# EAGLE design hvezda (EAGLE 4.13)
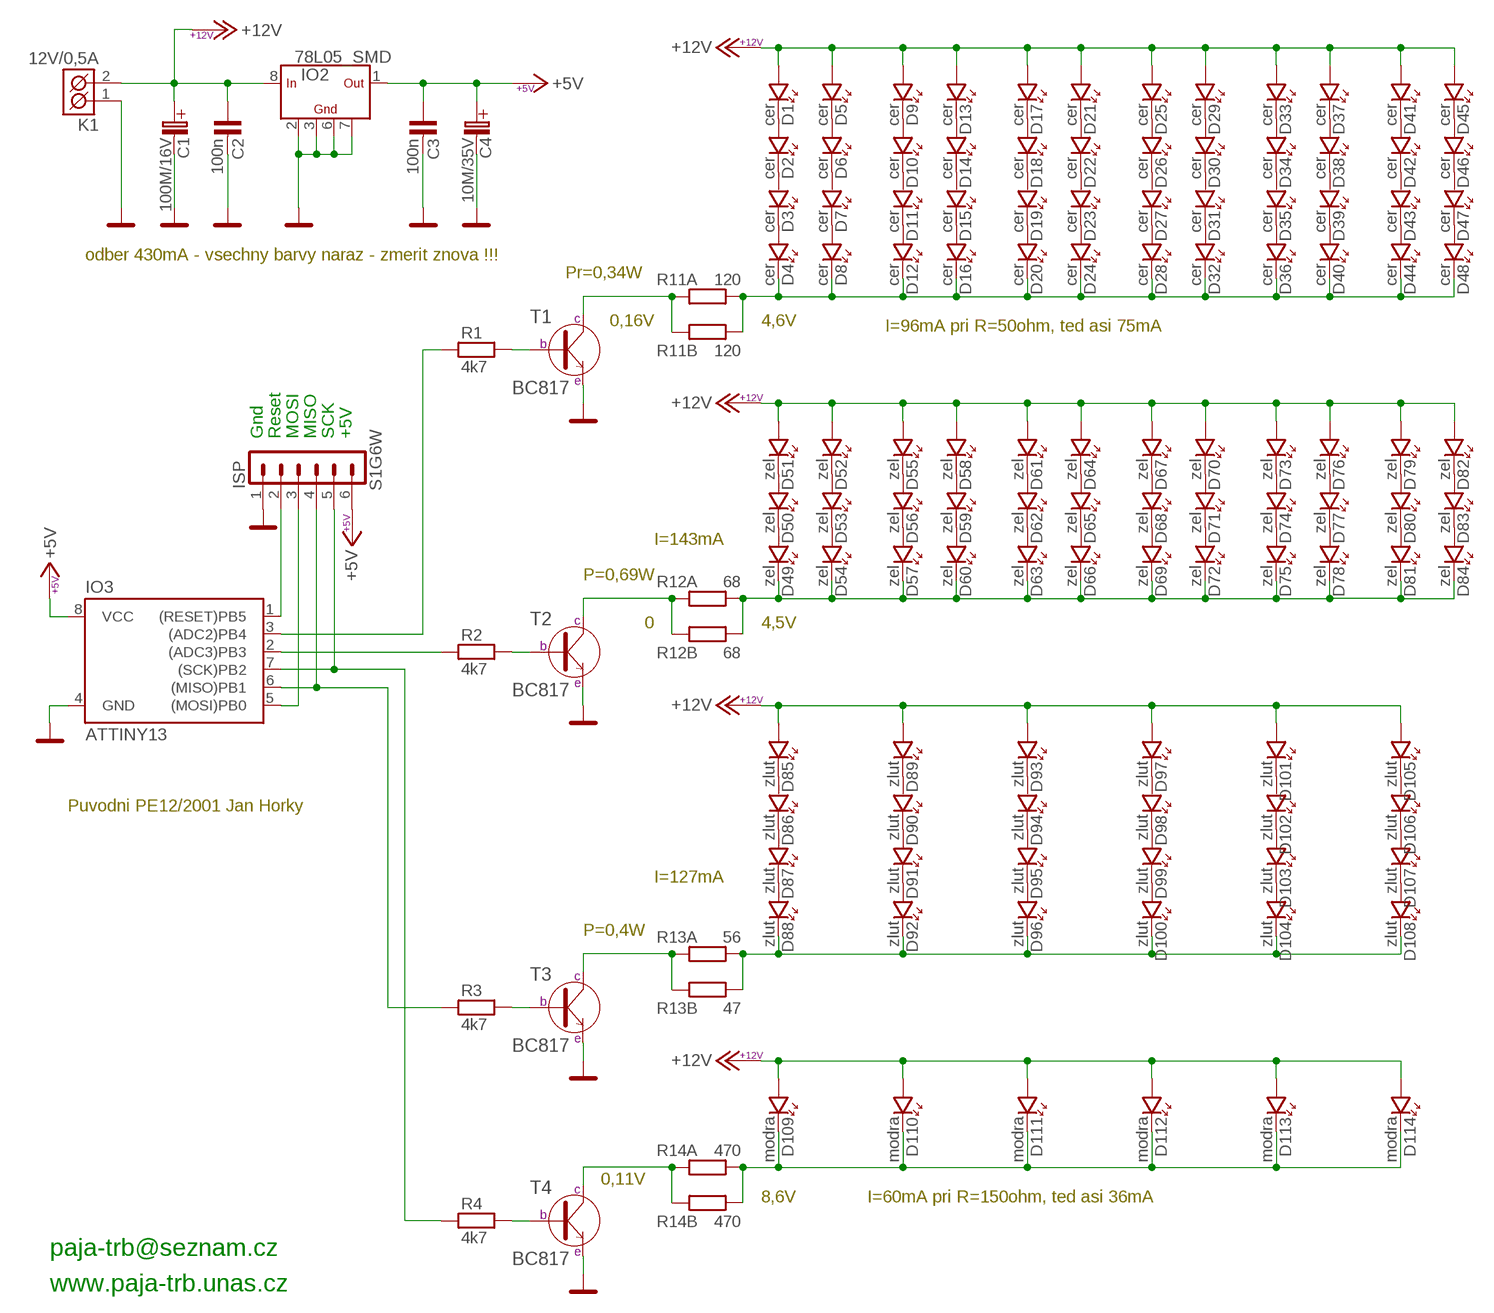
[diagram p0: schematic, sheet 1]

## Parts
C1  100M/16V  100M/16V_SMD  [C_EL-SMD_D]
C2  100n  C-KERAMIK_SMD_1206  [1206]
C3  100n  C-KERAMIK_SMD_1206  [1206]
C4  10M/35V  10M/35V_SMD  [C_EL-SMD_C]
D1  cer  LED_SMD_1206  [P1206]
D2  cer  LED_SMD_1206  [P1206]
D3  cer  LED_SMD_1206  [P1206]
D4  cer  LED_SMD_1206  [P1206]
D5  cer  LED_SMD_1206  [P1206]
D6  cer  LED_SMD_1206  [P1206]
D7  cer  LED_SMD_1206  [P1206]
D8  cer  LED_SMD_1206  [P1206]
D9  cer  LED_SMD_1206  [P1206]
D10  cer  LED_SMD_1206  [P1206]
D11  cer  LED_SMD_1206  [P1206]
D12  cer  LED_SMD_1206  [P1206]
D13  cer  LED_SMD_1206  [P1206]
D14  cer  LED_SMD_1206  [P1206]
D15  cer  LED_SMD_1206  [P1206]
D16  cer  LED_SMD_1206  [P1206]
D17  cer  LED_SMD_1206  [P1206]
D18  cer  LED_SMD_1206  [P1206]
D19  cer  LED_SMD_1206  [P1206]
D20  cer  LED_SMD_1206  [P1206]
D21  cer  LED_SMD_1206  [P1206]
D22  cer  LED_SMD_1206  [P1206]
D23  cer  LED_SMD_1206  [P1206]
D24  cer  LED_SMD_1206  [P1206]
D25  cer  LED_SMD_1206  [P1206]
D26  cer  LED_SMD_1206  [P1206]
D27  cer  LED_SMD_1206  [P1206]
D28  cer  LED_SMD_1206  [P1206]
D29  cer  LED_SMD_1206  [P1206]
D30  cer  LED_SMD_1206  [P1206]
D31  cer  LED_SMD_1206  [P1206]
D32  cer  LED_SMD_1206  [P1206]
D33  cer  LED_SMD_1206  [P1206]
D34  cer  LED_SMD_1206  [P1206]
D35  cer  LED_SMD_1206  [P1206]
D36  cer  LED_SMD_1206  [P1206]
D37  cer  LED_SMD_1206  [P1206]
D38  cer  LED_SMD_1206  [P1206]
D39  cer  LED_SMD_1206  [P1206]
D40  cer  LED_SMD_1206  [P1206]
D41  cer  LED_SMD_1206  [P1206]
D42  cer  LED_SMD_1206  [P1206]
D43  cer  LED_SMD_1206  [P1206]
D44  cer  LED_SMD_1206  [P1206]
D45  cer  LED_SMD_1206  [P1206]
D46  cer  LED_SMD_1206  [P1206]
D47  cer  LED_SMD_1206  [P1206]
D48  cer  LED_SMD_1206  [P1206]
D49  zel  LED_SMD_1206  [P1206]
D50  zel  LED_SMD_1206  [P1206]
D51  zel  LED_SMD_1206  [P1206]
D52  zel  LED_SMD_1206  [P1206]
D53  zel  LED_SMD_1206  [P1206]
D54  zel  LED_SMD_1206  [P1206]
D55  zel  LED_SMD_1206  [P1206]
D56  zel  LED_SMD_1206  [P1206]
D57  zel  LED_SMD_1206  [P1206]
D58  zel  LED_SMD_1206  [P1206]
D59  zel  LED_SMD_1206  [P1206]
D60  zel  LED_SMD_1206  [P1206]
D61  zel  LED_SMD_1206  [P1206]
D62  zel  LED_SMD_1206  [P1206]
D63  zel  LED_SMD_1206  [P1206]
D64  zel  LED_SMD_1206  [P1206]
D65  zel  LED_SMD_1206  [P1206]
D66  zel  LED_SMD_1206  [P1206]
D67  zel  LED_SMD_1206  [P1206]
D68  zel  LED_SMD_1206  [P1206]
D69  zel  LED_SMD_1206  [P1206]
D70  zel  LED_SMD_1206  [P1206]
D71  zel  LED_SMD_1206  [P1206]
D72  zel  LED_SMD_1206  [P1206]
D73  zel  LED_SMD_1206  [P1206]
D74  zel  LED_SMD_1206  [P1206]
D75  zel  LED_SMD_1206  [P1206]
D76  zel  LED_SMD_1206  [P1206]
D77  zel  LED_SMD_1206  [P1206]
D78  zel  LED_SMD_1206  [P1206]
D79  zel  LED_SMD_1206  [P1206]
D80  zel  LED_SMD_1206  [P1206]
D81  zel  LED_SMD_1206  [P1206]
D82  zel  LED_SMD_1206  [P1206]
D83  zel  LED_SMD_1206  [P1206]
D84  zel  LED_SMD_1206  [P1206]
D85  zlut  LED_SMD_1206  [P1206]
D86  zlut  LED_SMD_1206  [P1206]
D87  zlut  LED_SMD_1206  [P1206]
D88  zlut  LED_SMD_1206  [P1206]
D89  zlut  LED_SMD_1206  [P1206]
D90  zlut  LED_SMD_1206  [P1206]
D91  zlut  LED_SMD_1206  [P1206]
D92  zlut  LED_SMD_1206  [P1206]
D93  zlut  LED_SMD_1206  [P1206]
D94  zlut  LED_SMD_1206  [P1206]
D95  zlut  LED_SMD_1206  [P1206]
D96  zlut  LED_SMD_1206  [P1206]
D97  zlut  LED_SMD_1206  [P1206]
D98  zlut  LED_SMD_1206  [P1206]
D99  zlut  LED_SMD_1206  [P1206]
D100  zlut  LED_SMD_1206  [P1206]
D101  zlut  LED_SMD_1206  [P1206]
D102  zlut  LED_SMD_1206  [P1206]
D103  zlut  LED_SMD_1206  [P1206]
D104  zlut  LED_SMD_1206  [P1206]
D105  zlut  LED_SMD_1206  [P1206]
D106  zlut  LED_SMD_1206  [P1206]
D107  zlut  LED_SMD_1206  [P1206]
D108  zlut  LED_SMD_1206  [P1206]
D109  modra  LED_SMD_1206  [P1206]
D110  modra  LED_SMD_1206  [P1206]
D111  modra  LED_SMD_1206  [P1206]
D112  modra  LED_SMD_1206  [P1206]
D113  modra  LED_SMD_1206  [P1206]
D114  modra  LED_SMD_1206  [P1206]
IO2  78L05_SMD  78L_SMD-SO8  [SO08]
IO3  ATTINY13  [SOIC08]
ISP  S1G6W  S1G6_JUMP  [S1G6_JUM]
K1  12V/0,5A  ARK500/2  [ARK500/2]
R1  4k7  R_SMD_1206  [1206]
R2  4k7  R_SMD_1206  [1206]
R3  4k7  R_SMD_1206  [1206]
R4  4k7  R_SMD_1206  [1206]
R11A  120  R_SMD_1206  [1206]
R11B  120  R_SMD_1206  [1206]
R12A  68  R_SMD_1206  [1206]
R12B  68  R_SMD_1206  [1206]
R13A  56  R_SMD_1206  [1206]
R13B  47  R_SMD_1206  [1206]
R14A  470  R_SMD_1206  [1206]
R14B  470  R_SMD_1206  [1206]
T1  BC817  [SOT-23]
T2  BC817  [SOT-23]
T3  BC817  [SOT-23]
T4  BC817  [SOT-23]

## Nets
+5V: C3.1 C4.+(C_EL+) IO2.1(OUT) IO3.8(VCC) ISP.6
+12V: C1.+(C_EL+) C2.1 D1.A D5.A D9.A D13.A D17.A D21.A D25.A D29.A D33.A D37.A D41.A D45.A D51.A D52.A D55.A D58.A D61.A D64.A D67.A D70.A D73.A D76.A D79.A D82.A D85.A D89.A D93.A D97.A D101.A D105.A D109.A D110.A D111.A D112.A D113.A D114.A IO2.8(IN) K1.2(K2)
GND: C1.-(C_EL-) C2.2 C3.2 C4.-(C_EL-) IO2.2(GND) IO2.3(GND) IO2.6(GND) IO2.7(GND) IO3.4(GND) ISP.1 K1.1(K1) T1.1(E) T2.1(E) T3.1(E) T4.1(E)
K_CER: D4.K D8.K D12.K D16.K D20.K D24.K D28.K D32.K D36.K D40.K D44.K D48.K R11A.2 R11B.2
K_NEVIM: D109.K D110.K D111.K D112.K D113.K D114.K R14A.2 R14B.2
K_ZEL: D49.K D54.K D57.K D60.K D63.K D66.K D69.K D72.K D75.K D78.K D81.K D84.K R12A.2 R12B.2
K_ZLUT: D88.K D92.K D96.K D100.K D104.K D108.K R13A.2 R13B.2
N$1: D1.K D2.A
N$2: D2.K D3.A
N$3: D3.K D4.A
N$4: D5.K D6.A
N$5: D50.A D51.K
N$6: D6.K D7.A
N$7: D9.K D10.A
N$8: D7.K D8.A
N$9: D10.K D11.A
N$10: D11.K D12.A
N$11: D13.K D14.A
N$12: D14.K D15.A
N$13: D15.K D16.A
N$14: D17.K D18.A
N$15: D18.K D19.A
N$16: D19.K D20.A
N$17: D21.K D22.A
N$18: D22.K D23.A
N$19: D23.K D24.A
N$20: D25.K D26.A
N$21: D26.K D27.A
N$22: D27.K D28.A
N$23: D29.K D30.A
N$24: D30.K D31.A
N$25: D31.K D32.A
N$26: D33.K D34.A
N$27: D34.K D35.A
N$28: D35.K D36.A
N$29: D37.K D38.A
N$30: D38.K D39.A
N$31: D39.K D40.A
N$32: D41.K D42.A
N$33: D42.K D43.A
N$34: D43.K D44.A
N$35: D45.K D46.A
N$36: D46.K D47.A
N$37: D47.K D48.A
N$38: D49.A D50.K
N$39: D52.K D53.A
N$40: D53.K D54.A
N$41: D55.K D56.A
N$42: D56.K D57.A
N$43: D58.K D59.A
N$44: D59.K D60.A
N$45: D61.K D62.A
N$46: D62.K D63.A
N$47: D64.K D65.A
N$48: D65.K D66.A
N$49: D67.K D68.A
N$50: D68.K D69.A
N$51: D70.K D71.A
N$52: D71.K D72.A
N$53: D73.K D74.A
N$54: D74.K D75.A
N$55: D76.K D77.A
N$56: D77.K D78.A
N$57: D79.K D80.A
N$58: D80.K D81.A
N$59: D82.K D83.A
N$60: D83.K D84.A
N$61: IO3.1((RESET)PB5) ISP.2
N$67: D85.K D86.A
N$68: D86.K D87.A
N$69: D87.K D88.A
N$71: D89.K D90.A
N$72: D90.K D91.A
N$73: D91.K D92.A
N$74: D93.K D94.A
N$75: D94.K D95.A
N$76: D95.K D96.A
N$77: D97.K D98.A
N$78: D98.K D99.A
N$79: D99.K D100.A
N$80: D101.K D102.A
N$81: D102.K D103.A
N$82: D103.K D104.A
N$83: D105.K D106.A
N$84: D106.K D107.A
N$85: D107.K D108.A
N$88: IO3.2((ADC3)PB3) R2.1
N$91: R3.2 T3.2(B)
N$92: R13A.1 R13B.1 T3.3(C)
N$93: R11A.1 R11B.1 T1.3(C)
N$94: R12A.1 R12B.1 T2.3(C)
N$95: R1.2 T1.2(B)
N$96: R2.2 T2.2(B)
N$97: IO3.3((ADC2)PB4) R1.1
N$98: IO3.5((MOSI)PB0) ISP.3
N$99: IO3.6((MISO)PB1) ISP.4 R3.1
N$121: R4.2 T4.2(B)
N$122: R14A.1 R14B.1 T4.3(C)
N$123: IO3.7((SCK)PB2) ISP.5 R4.1
Unconnected: IO2.4 IO2.5

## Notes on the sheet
- odber 430mA - vsechny barvy naraz - zmerit znova !!!
- Pr=0,34W
- 0,16V | 4,6V
- I=96mA pri R=50ohm, ted asi 75mA
- Gnd | Reset | MOSI | MISO | SCK | +5V
- I=143mA
- P=0,69W
- 0 | 4,5V
- Puvodni PE12/2001 Jan Horky
- I=127mA
- P=0,4W
- 0,11V
- 8,6V | I=60mA pri R=150ohm, ted asi 36mA
- paja-trb@seznam.cz
- www.paja-trb.unas.cz

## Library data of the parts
C1 = #PaJa_C-el_eagle413:100M/16V
C2 C3 = #PaJa_20:C-KERAMIK: Kondenzator - keramicky
C4 = #PaJa_C-el_eagle413:10M/35V
D1-D114 = #PaJa_20:LED: LED - jednobarevna
IO2 = #PaJa_22:78L??_SMD-SO8: Stabilizátor SMD - 100mA ?? - napeti => 05, 08, 09, 12, 15
IO3 = #PaJa_22:ATTINY13
ISP = __pokusy:S1G6_JUMP
K1 = __pokusy:ARK500/2: Svorkovnice - roztec 5mm - dvojita
R1-R4 R11A R11B R12A R12B R13A R13B R14A R14B = #PaJa_20:R: Rezistor
T1-T4 = #PaJa_20:BC817: SMD tranzistor - NPN - ekv. BC337

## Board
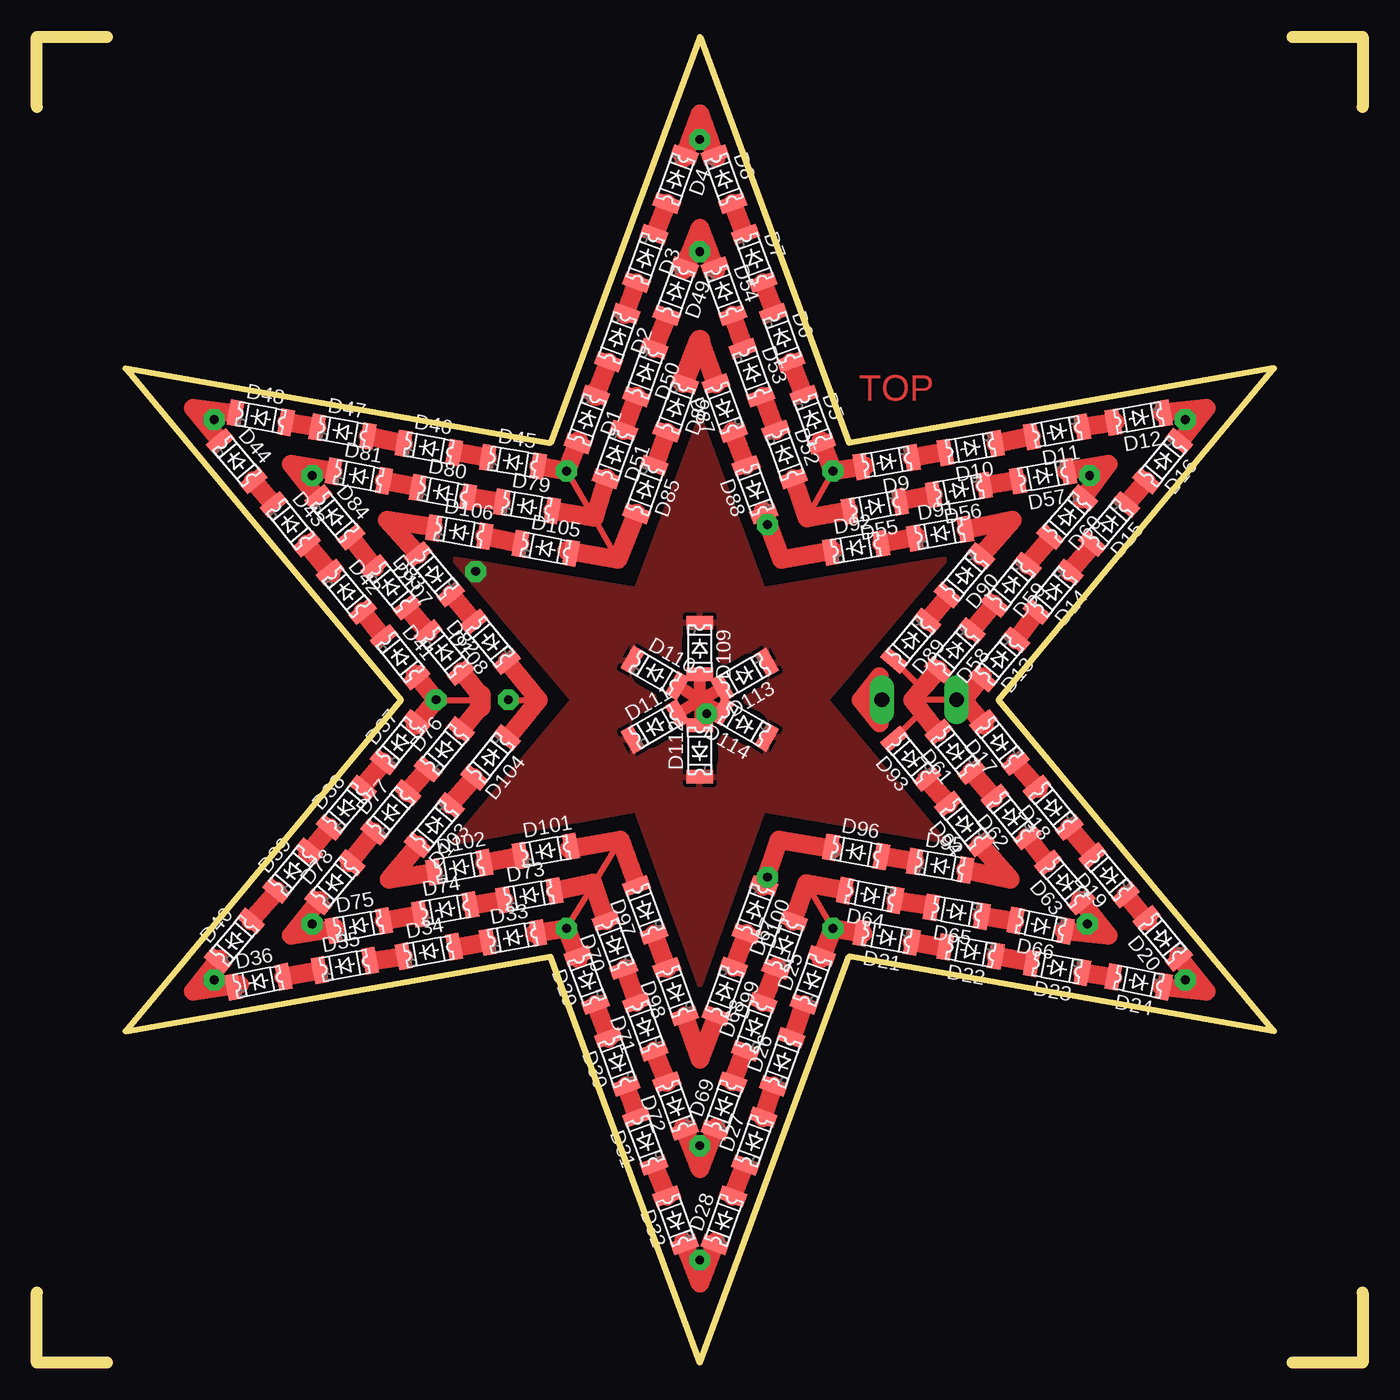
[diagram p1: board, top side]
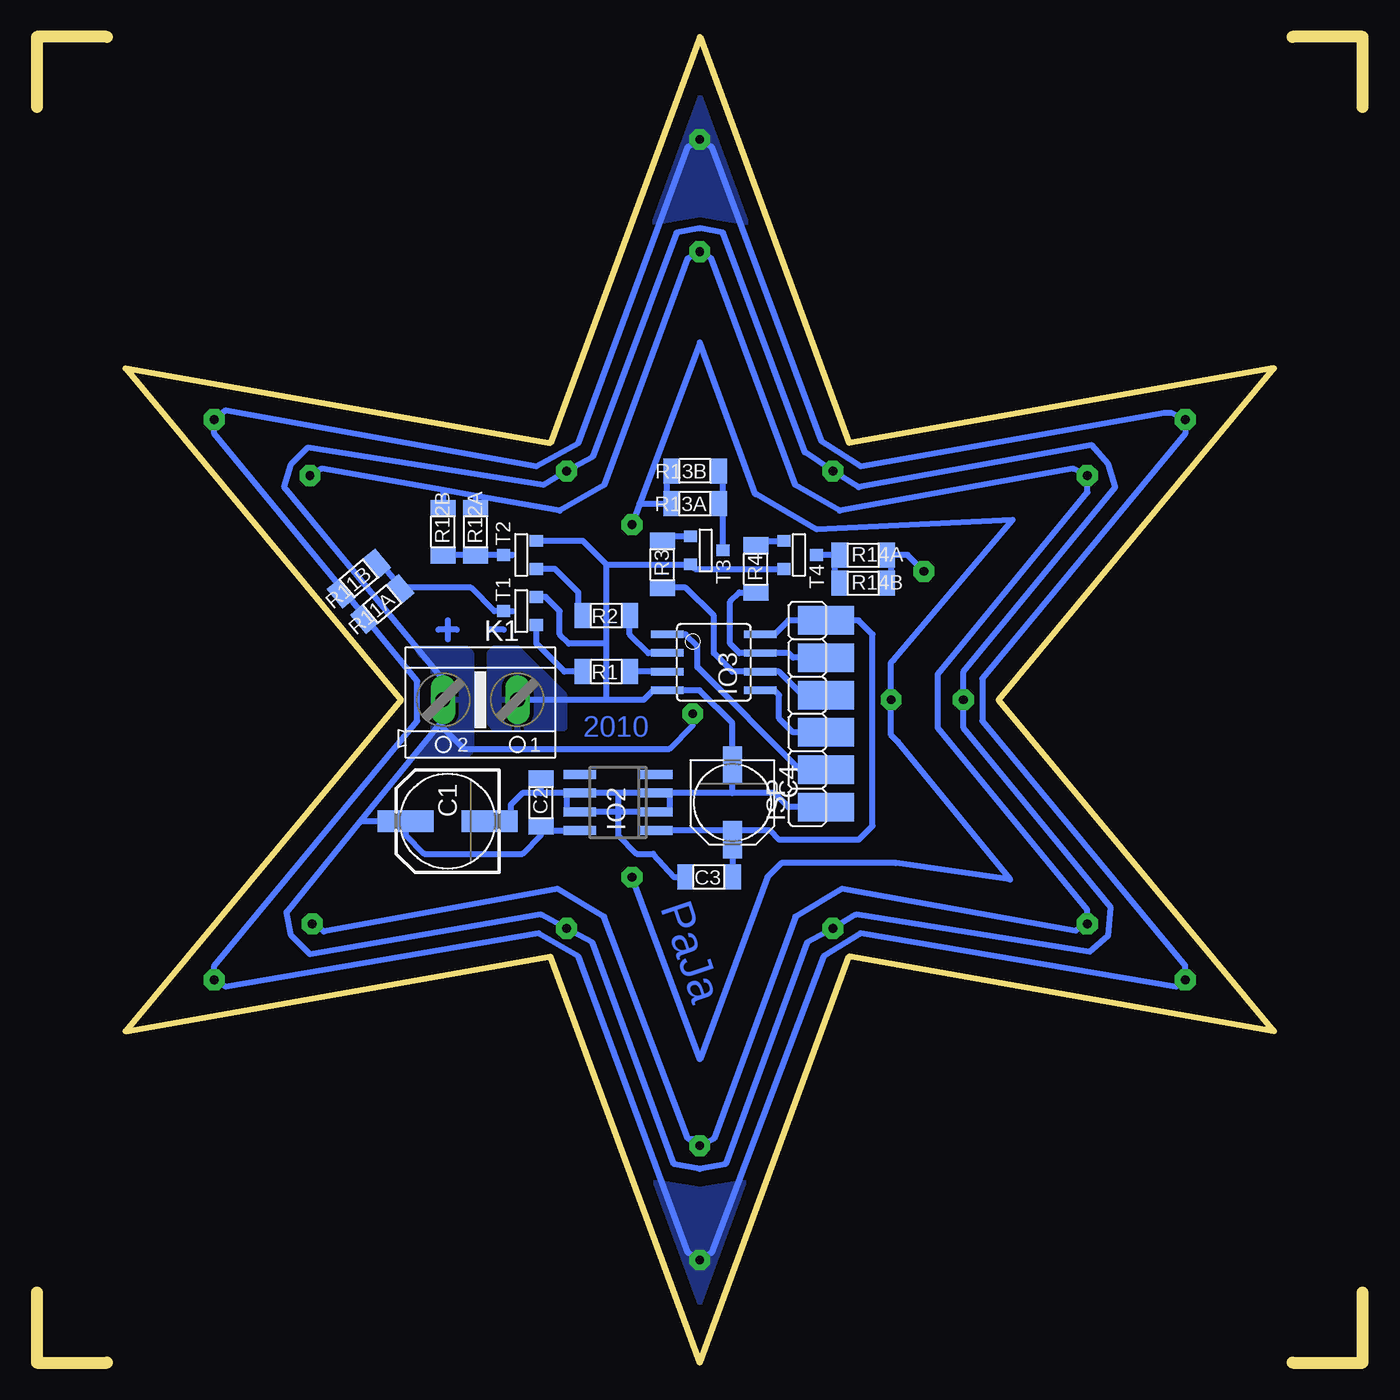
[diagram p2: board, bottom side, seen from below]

Size 90.17 x 90.17 mm. Coordinates in mm from the lower left corner, seen from the top.
Outline: 0,4.76 0,0 4.76,0
Outline: 85.41,0 90.17,0 90.17,4.76
Outline: 90.17,85.41 90.17,90.17 85.41,90.17
Outline: 4.76,90.17 0,90.17 0,85.41
Outline: 45.08,90.17 34.93,62.55 6.03,67.63 24.76,45.09 6.03,22.54 34.93,27.62 45.08,0 55.25,27.62 84.14,22.54 65.41,45.09 84.14,67.63 55.25,62.55 45.08,90.17
Copper layers (1*16): Top 0.035mm / dielectric 1.5mm / Bottom 0.035mm
Design rules "default": minimum track width 10mil, minimum drill 24mil, track to track 8mil, track to pad 8mil, pad to pad 8mil, via to via 8mil, smd to smd 8mil, copper to edge 40mil, drill to drill 8mil, minimum pad ring 10mil, minimum via ring 8mil, stop-mask expansion 4mil, vias tented up to drill 0mil, thermal gap 10mil
tRestrict: 3 lines

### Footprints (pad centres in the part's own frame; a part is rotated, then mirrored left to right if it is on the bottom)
C_EL-SMD_D = smd 3.81 x 1.473: + 2.857,0; - -2.857,0
1206 = smd 1.143 x 1.702: 1 -1.587,0; 2 1.587,0
C_EL-SMD_C = smd 2.54 x 1.27: + 2.54,0; - -2.54,0
P1206 = smd 0.914 x 1.778: A 1.905,0; K -1.587,0
SO08 = smd 0.6 x 2.2: 1 -1.905,-2.6; 2 -0.635,-2.6; 3 0.635,-2.6; 4 1.905,-2.6; 5 1.905,2.6; 6 0.635,2.6; 7 -0.635,2.6; 8 -1.905,2.6
SOIC08 = smd 2.2 x 0.5: 1 -3.154,1.905; 2 -3.154,0.645; 3 -3.154,-0.625; 4 -3.154,-1.895; 5 3.154,-1.905; 6 3.154,-0.635; 7 3.154,0.635; 8 3.154,1.905
S1G6_JUM = smd 1.93 x 3.81: 1 -6.35,-1.27; 2 -3.81,-1.27; 3 -1.27,-1.27; 4 1.27,-1.27; 5 3.81,-1.27; 6 6.35,-1.27
ARK500/2 = drill 1 pad 1.676 long: 1 -2.54,0; 2 2.54,0
SOT-23 = smd 0.787 x 0.889: 1 0.953,-0.953; 2 -0.953,-0.953; 3 0,1.27

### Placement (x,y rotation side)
C1  62.23,36.83 180 bottom
C2  55.88,38.1 90 bottom
C3  44.45,33.02 180 bottom
C4  42.86,38.1 270 bottom
D1  37.47,64.29 250 top
D2  39.53,69.85 250 top
D3  41.43,75.25 250 top
D4  43.5,80.65 250 top
D5  52.7,64.29 290 top
D6  50.64,69.85 290 top
D7  48.74,75.25 290 top
D8  46.67,80.65 290 top
D9  57.94,61.28 189.8 top
D10  63.66,62.23 190 top
D11  69.53,63.34 190.6 top
D12  75.09,64.29 190 top
D13  65.56,47.94 229.9 top
D14  69.21,52.55 230.1 top
D15  73.02,57.15 229.4 top
D16  76.68,61.44 230.4 top
D17  65.56,42.07 128.7 top
D18  69.21,37.62 129.3 top
D19  73.02,33.02 130.1 top
D20  76.68,28.73 129.4 top
D21  57.94,28.89 169.8 top
D22  63.66,27.94 169.9 top
D23  69.53,26.83 169.8 top
D24  75.09,25.88 169 top
D25  52.71,25.88 70 top
D26  50.64,20.32 70 top
D27  48.74,14.92 70 top
D28  46.67,9.53 70 top
D29  37.47,25.88 110 top
D30  39.53,20.32 110 top
D31  41.43,14.92 110 top
D32  43.5,9.53 110 top
D33  32.23,28.89 10.3 top
D34  26.51,27.94 10.8 top
D35  20.8,26.99 10.7 top
D36  14.92,25.88 11.4 top
D37  24.61,42.07 50.5 top
D38  20.96,37.62 49.8 top
D39  17.3,33.34 50.2 top
D40  13.33,28.57 50 top
D41  24.61,48.1 309.1 top
D42  20.96,52.55 309.4 top
D43  17.15,57.15 309.6 top
D44  13.49,61.44 310.2 top
D45  32.23,61.28 350.6 top
D46  26.51,62.23 349.8 top
D47  20.64,63.34 350 top
D48  15.08,64.29 349.5 top
D49  43.5,73.03 250 top
D50  41.43,67.47 250 top
D51  39.37,61.91 250 top
D52  50.8,61.91 290 top
D53  48.58,67.47 290 top
D54  46.67,73.02 290 top
D55  57.15,58.26 190.4 top
D56  62.87,59.37 190.3 top
D57  68.58,60.33 190.4 top
D58  62.55,48.58 229.6 top
D59  66.36,53.02 230.7 top
D60  70.17,57.63 229.1 top
D61  62.55,41.43 129.4 top
D62  66.36,36.99 129.3 top
D63  70.01,32.54 130.4 top
D64  56.83,31.75 169.2 top
D65  62.71,30.64 170.2 top
D66  68.42,29.69 168.4 top
D67  50.8,28.26 70 top
D68  48.74,22.7 70 top
D69  46.67,17.3 70 top
D70  39.37,28.26 110 top
D71  41.43,22.7 110 top
D72  43.5,17.3 110 top
D73  33.34,31.75 10.1 top
D74  27.62,30.8 10.3 top
D75  21.75,29.69 10.7 top
D76  27.62,41.59 50.3 top
D77  23.97,37.31 50.1 top
D78  20.16,32.54 50 top
D79  33.18,58.26 350.5 top
D80  27.46,59.21 349.5 top
D81  21.75,60.33 349.4 top
D82  27.62,48.42 309.6 top
D83  23.97,52.86 309.6 top
D84  20.16,57.63 309.9 top
D85  41.43,59.53 250 top
D86  43.5,65.09 250 top
D87  46.83,64.77 110 top
D88  48.9,59.21 110 top
D89  59.53,49.21 229.7 top
D90  63.18,53.66 229.8 top
D91  61.28,56.36 10 top
D92  55.56,55.4 9.5 top
D93  59.53,40.96 130 top
D94  63.18,36.51 129.2 top
D95  61.28,33.81 350.6 top
D96  55.56,34.77 349.6 top
D97  41.43,30.64 110 top
D98  43.5,25.08 110 top
D99  46.83,25.4 250 top
D100  48.9,30.96 250 top
D101  34.45,34.77 10.3 top
D102  28.58,33.66 10.5 top
D103  27.15,36.67 230.1 top
D104  30.96,41.28 230.8 top
D105  34.45,55.4 349.5 top
D106  28.57,56.52 350.7 top
D107  27.15,53.5 129.7 top
D108  30.96,48.89 129.5 top
D109  45.09,48.74 270 top
D110  41.91,46.99 330 top
D111  41.91,43.18 30 top
D112  45.08,41.43 90 top
D113  48.26,46.83 210 top
D114  48.26,43.34 150 top
IO2  50.64,38.1 90 bottom
IO3  44.13,47.62 0 bottom
ISP  37.78,44.13 90 bottom
K1  60.01,45.09 180 bottom
R1  51.44,46.99 180 bottom
R2  51.44,50.8 180 bottom
R3  47.62,54.29 90 bottom
R4  41.27,53.98 90 bottom
R11A  66.67,51.59 220 bottom
R11B  68.26,53.34 220 bottom
R12A  60.32,56.51 90 bottom
R12B  62.55,56.52 90 bottom
R13A  45.4,58.42 180 bottom
R13B  45.4,60.64 180 bottom
R14A  33.97,54.93 0 bottom
R14B  33.97,53.02 0 bottom
T1  57.15,51.12 90 bottom
T2  57.15,54.93 90 bottom
T3  44.77,55.24 270 bottom
T4  38.42,54.93 270 bottom

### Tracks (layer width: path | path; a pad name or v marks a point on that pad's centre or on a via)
+5V
  Bottom 0.406: 40.01,49.53 40.96,49.55 | 42.7,36.04 42.53,36.06 42.55,36.07 42.55,36.2 | 42.7,36.04 42.86,35.88 C4.+ 42.86,35.24 | 42.86,36.2 42.86,36.19 42.7,36.04 | 42.86,36.2 IO2.1 | 42.86,35.24 C3.1 | 42.86,35.24 | ISP.6 36.83,51.12 | ISP.6 34.29,50.48 33.34,49.53 33.34,36.51 34.29,35.56 39.69,35.56 40.32,36.2 42.86,36.2 | 40.01,49.53 39.05,50.48 ISP.6 | 40.01,49.53 IO3.8
+12V  (via drill 0.6 pad 1.42)
  Top 0.406: 38.73,60.17 D51.A | D52.A 51.44,60.17 | 55.25,57.94 D55.A | D64.A 54.93,32.07 | 51.44,30 D67.A | D70.A 38.73,30 | 28.73,43.18 D76.A 28.89,43.02 | 28.89,46.99 D82.A | 40.8,57.78 D85.A | 35.24,32.07 D73.A | 61.28,42.86 D61.A 59.21,45.03 59.21,45.09 K1.2 62.39,45.09 63.02,45.09 | D79.A 35.08,57.94 | 34.13,60.96 D45.A | 53.34,62.71 D5.A | D58.A 61.28,47.15 | D41.A 25.88,46.67 25.72,46.83 | D29.A 36.83,27.62 36.83,27.46 | 56.2,29.21 D21.A | D13.A 64.45,46.51 64.29,46.67 | D97.A 40.8,32.38 40.8,32.54 | v36.04,60.64 37.88,57.43 | 37.88,57.43 39.69,54.29 39.53,54.45 | 39.53,54.45 39.58,54.48 | 39.53,54.45 39.53,54.61 | 36.04,55.24 D105.A | 37.77,57.62 37.78,57.63 D79.A | 37.88,57.43 37.94,57.47 D79.A | D1.A 36.83,62.55 36.83,62.71 | v36.04,29.53 37.78,32.38 | 37.78,32.38 39.69,35.56 | 36.19,34.93 D101.A | 37.78,32.38 37.82,32.62 | 33.81,29.21 D33.A | v54.13,29.53 52.39,32.54 52.23,32.7 52.35,32.61 | D25.A 53.34,27.62 53.34,27.46 | 60.21,45.84 60.17,45.88 60.17,45.89 D89.A | 60.17,44.29 | D93.A 60.17,44.28 60.17,44.29 | D17.A 64.45,43.48 64.45,43.34 | v54.13,60.64 52.39,57.47 52.23,57.31 52.38,57.45 | 56.36,60.96 D9.A | v27.15,45.09 30.16,45.09 | 25.72,43.34 D37.A | D112.A
  Top 0.813: 45.08,45.09 D109.A | 45.08,45.09 D110.A | 45.08,45.09 D114.A | 45.08,45.09 D113.A | 45.08,45.09 D111.A | v45.56,44.13 45.08,45.09 | 45.08,45.09 D112.A
  Top 1.016: v45.56,44.13 D112.A
  Top 1.27: D52.A 52.38,57.45 55.25,57.94 | 61.28,42.86 60.17,44.29 59.55,45.08 60.21,45.84 D58.A | 51.44,30 52.35,32.61 D64.A | 35.24,32.07 37.82,32.62 D70.A | 35.08,57.94 37.94,57.47 38.73,60.17 | 30.16,44.61 28.89,43.02 | 30.16,45.4 28.89,46.99 | 40.8,57.78 39.53,54.61 36.04,55.24 | 34.13,60.96 v36.04,60.64 36.83,62.71 | 33.81,29.21 v36.04,29.53 36.83,27.46 | 53.34,27.46 v54.13,29.53 56.2,29.21 | 53.34,62.71 v54.13,60.64 56.36,60.96 | 25.72,46.83 v27.15,45.09 25.72,43.34 | 64.29,46.67 63.02,45.09 64.45,43.34 | 40.8,32.54 39.69,35.56 36.19,34.93
  Top 1.422: 30.16,44.61 30.16,45.09 30.16,45.4
  Bottom 0.406: 62.39,45.09 62.71,46.67 73.34,59.53 72.87,61.12 71.76,62.23 55.72,59.69 v54.13,60.64 52.39,61.59 46.67,76.84 45.08,77.15 43.5,76.84 37.94,61.91 v36.04,60.64 34.29,59.53 18.42,62.39 17.3,61.12 16.83,59.53 27.15,46.99 v27.15,45.09 27.15,43.18 17.15,30.96 17.3,29.05 18.57,27.94 34.45,30.48 v36.04,29.53 37.78,28.57 43.34,13.49 45.08,13.18 46.83,13.49 52.39,28.57 v54.13,29.53 55.88,30.48 71.6,27.78 72.87,29.05 73.18,30.64 68.13,36.85 | 62.71,43.5 62.39,45.09 | 62.39,45.09 K1.2 | IO2.8 55.72,36.2 C2.1 55.88,35.88 57.15,34.61 63.82,34.61 65.09,35.88 C1.+ | C1.+ 66.36,36.83 | 68.13,36.85 62.71,43.5 | 68.13,36.85 68.11,36.83 C1.+ | v45.56,44.13 45.56,43.34 47.15,41.75 61.12,41.75 62.71,43.34 62.71,43.5
  pour Bottom: 60.96,48.58 60.64,48.26 60.64,41.59 60.96,41.27 64.45,41.27 63.18,42.55 63.18,47.31 64.13,48.26 64.13,48.58
GND
  Bottom 0.406: 54.13,38.73 IO2.6 50.16,38.73 | 54.13,38.73 55.88,38.73 | 55.72,39.69 C2.2 55.88,38.73 | IO2.7 54.13,37.46 54.13,38.73 | 47.62,37.46 47.15,37.46 47.15,38.73 | 51.44,45.09 51.44,48.9 | 51.44,48.9 51.44,54.29 | 51.44,54.29 53.02,55.88 55.56,55.88 | 51.44,48.9 53.97,48.9 54.61,49.53 54.61,51.12 55.56,52.07 T1.1 | 51.44,45.09 48.9,45.09 48.26,45.72 47.94,45.72 | 47.31,45.72 47.3,45.73 | 47.31,45.72 47.94,45.72 | 47.31,45.72 | 51.44,45.09 K1.1 | T1.1 | 55.56,55.88 | 55.56,55.88 T2.1 | 51.44,54.29 T3.1 45.4,53.98 T4.1 | C3.2 46.83,33.02 48.26,34.61 49.37,34.61 50.64,35.88 50.64,38.73 50.16,38.73 | 47.31,45.72 45.09,45.72 42.86,43.5 C4.- 42.86,38.73 | 55.88,38.73 57.15,38.73 57.94,37.94 57.94,36.83 C1.- | 42.86,38.73 47.15,38.73 | 42.86,38.73 40.01,38.73 39.05,37.78 ISP.1 | 50.16,38.73 IO2.3 47.15,38.73 | 47.62,37.46 IO2.2 | 47.62,37.46 52.7,37.46 | IO3.4 47.93,45.73 47.94,45.72
  pour Bottom: 54.29,45.4 57.47,48.58 59.05,48.58 59.37,48.26 59.37,43.5 59.05,43.18 54.29,43.18
K_CER  (via drill 0.6 pad 1.42)
  Top 0.406: D4.K 44.29,82.71 v45.08,83.18 45.88,82.71 D8.K | D32.K 44.29,7.46 v45.08,6.99 45.88,7.46 46.2,8.1 | D36.K 13.33,25.56 12.7,25.56 v12.06,26.04 12.06,26.99 D40.K | D20.K 77.95,27.15 v78.1,26.04 77.31,25.56 76.68,25.56 D24.K | D12.K 77.79,64.77 v78.1,64.13 78.26,63.34 | 78.26,63.34 | D16.K 77.79,62.71 78.26,63.34 | D48.K 13.02,64.61 v12.06,64.13 12.06,63.18 12.54,62.71 D44.K | 46.2,8.1 D28.K | 46.2,8.1 46.2,8.26
  Top 1.27: 13.02,64.61 10.64,64.93 12.06,63.18 | 76.52,64.61 79.53,64.93 77.79,62.71 | 43.97,8.26 45.08,5.4 46.2,8.26
  Bottom 0.406: 67.93,50.81 64.29,46.35 64.29,43.66 78.1,26.99 v78.1,26.04 77.31,25.56 56.04,29.21 53.34,27.62 45.88,7.46 v45.08,6.99 44.29,7.46 36.67,27.62 34.13,29.21 12.7,25.56 v12.06,26.04 12.06,26.99 25.88,43.66 25.88,46.51 12.06,63.18 v12.06,64.13 13.02,64.61 13.49,64.61 34.13,60.96 36.83,62.71 44.29,82.71 v45.08,83.18 45.88,82.71 53.34,62.55 56.2,60.96 77.31,64.77 v78.1,64.13 78.1,63.18 69.21,52.39 | 69.21,52.39 67.92,50.82 67.93,50.81 | 67.93,50.81 67.94,50.8 R11A.2 | 69.21,52.39 69.41,52.39 R11B.2
  pour Bottom (isolate 0.254): 41.27,12.38 45.09,11.75 48.9,12.38 45.09,2.22
  pour Bottom (isolate 0.254): 45.09,78.11 41.27,77.47 45.09,87.95 48.9,77.47
K_NEVIM  (via drill 0.6 pad 1.42)
  Bottom 0.406: R14A.2 | R14A.2 | R14A.2 | R14A.2 | v29.85,53.82 30.96,54.93 32.07,54.93 | 32.07,54.93 R14A.2 | R14B.2 32.07,53.02 32.07,54.93 | 32.07,54.93 R14A.2 | R14A.2
  pour Top (isolate 0.61): 28.42,54.61 36.51,45.09 28.42,35.4 40.8,37.62 45.09,25.72 49.37,37.62 61.59,35.56 53.66,45.09 61.75,54.61 49.37,52.55 45.09,64.14 40.8,52.55
K_ZEL  (via drill 0.6 pad 1.42)
  Top 0.406: 44.29,75.09 v45.08,75.57 45.88,75.09 D54.K | D72.K 44.29,15.24 v45.08,14.76 45.88,15.24 46.2,15.88 | 46.2,15.88 D69.K | D81.K 19.53,60.64 v18.73,60.33 18.73,59.21 D84.K | D57.K 70.8,60.8 v71.6,60.33 71.6,59.37 71.12,58.74 D60.K | D66.K 70.01,29.37 70.64,29.37 v71.44,29.84 71.44,30.8 D63.K | D78.K 18.57,30.64 v18.73,29.84 19.53,29.37 20.17,29.37 D75.K | 46.2,15.88 46.2,16.03
  Top 1.27: 70.01,60.64 72.87,61.12 71.12,58.74 | 43.97,16.03 45.08,13.18 46.2,16.03
  Top 1.422: 44.29,75.09 D49.K
  Bottom 0.406: 45.88,15.24 51.59,30.32 54.77,32.23 70.63,29.32 v71.44,29.84 71.28,29.69 | v71.6,60.33 70.8,60.8 62.5,59.34 | 60.29,58.95 54.61,57.94 51.59,59.69 45.9,75.1 45.88,75.09 v45.08,75.57 44.29,75.09 38.58,59.69 35.56,57.94 19.69,60.8 v18.73,60.33 18.73,59.21 18.72,59.2 28.89,46.83 28.89,43.18 18.73,30.8 v18.73,29.84 19.53,29.37 35.4,32.23 38.58,30.32 44.13,15.24 v45.08,14.76 45.88,15.24 | 60.29,58.95 62.5,59.34 | 45.88,15.24 45.08,15.24 | 60.29,58.95 60.33,58.91 R12A.2 | 62.5,59.34 62.55,59.29 R12B.2
K_ZLUT  (via drill 0.6 pad 1.42)
  Top 0.406: 31.91,42.55 D104.K 31.91,42.39 32.07,42.55 | 53.97,35.08 D96.K 54.13,34.93 54.14,34.95 54.29,34.93 | 49.53,57.78 D88.K 49.37,57.78 49.53,57.63 | 54.29,55.24 54.14,55.22 54.13,55.24 D92.K | 31.91,47.78 31.99,47.69 31.91,47.63 D108.K | v32.07,45.09 34.13,45.09 | v49.69,33.02 49.37,32.23 | 49.37,32.23 49.37,32.38 | 49.37,32.23 D100.K | v49.69,56.99 49.37,57.94
  Top 1.27: 49.37,32.38 50.48,35.56 54.14,34.95 | 49.37,57.94 50.64,54.61 54.14,55.22 | 32.07,42.55 34.13,45.09 31.99,47.69
  Top 1.422: v49.69,56.99 49.53,57.63
  Bottom 0.406: 49.16,58.4 45.08,69.37 41.28,59.05 41.27,59.05 37.15,56.67 23.81,57.31 31.91,47.78 32.07,47.63 v32.07,45.09 32.07,42.7 31.59,42.23 23.97,32.86 31.75,33.97 39.53,33.97 40.48,33.02 45.08,20.64 v49.69,33.02 | 49.16,58.4 v49.69,56.99 | v49.69,56.99 | v49.69,33.02 | 49.16,58.4 49.21,58.42 47.31,58.42 | R13B.2 47.31,60.64 47.31,58.42 | 47.31,58.42 R13A.2
N$1
  Top 1.27: 38.1,66.04 D2.A
  Top 1.422: D1.K 38.1,66.04
N$2
  Top 0.406: D2.K 40.01,71.28
  Top 1.27: 40.01,71.28 D3.A
N$3
  Top 0.406: D3.K 42.07,76.84
  Top 1.27: 42.07,76.84 D4.A
N$4
  Top 0.406: 52.07,66.04 D5.K
  Top 1.27: D6.A 52.07,66.04
N$5
  Top 0.406: 40.8,65.72 D50.A
  Top 1.27: D51.K 40.8,65.72
N$6
  Top 0.406: D6.K 50.16,71.44
  Top 1.27: 50.16,71.44 D7.A
N$7
  Top 0.406: D10.A 61.59,61.91
  Top 1.27: 61.59,61.91 D9.K
N$8
  Top 0.406: D7.K 48.1,76.84
  Top 1.27: 48.1,76.84 D8.A
N$9
  Top 0.406: 67.63,63.02 D11.A
  Top 1.27: D10.K 67.63,63.02
N$10
  Top 0.406: 73.34,63.98 D12.A
  Top 1.27: D11.K 73.34,63.98
N$11
  Top 0.406: 67.94,50.96 D14.A
  Top 1.27: D13.K 67.94,50.96
N$12
  Top 0.406: 71.76,55.56 D15.A
  Top 1.27: D14.K 71.76,55.56
N$13
  Top 0.406: D15.K 74.14,58.42
  Top 1.27: 74.14,58.42 D16.A
N$14
  Top 0.406: 68.1,39.05 D18.A
  Top 1.27: D17.K 68.1,39.05
N$15
  Top 0.406: D19.A 71.76,34.61
  Top 1.27: 71.76,34.61 D18.K
N$16
  Top 0.406: D20.A 75.57,30
  Top 1.27: 75.57,30 D19.K
N$17
  Top 0.406: D22.A 61.59,28.26
  Top 1.27: 61.59,28.26 D21.K
N$18
  Top 0.406: 67.31,27.3 D23.A
  Top 1.27: D22.K 67.31,27.3
N$19
  Top 0.406: D24.A 73.18,26.19
  Top 1.27: 73.18,26.19 D23.K
N$20
  Top 0.406: D26.A 51.44,22.23
  Top 1.27: 51.44,22.23 D25.K
N$21
  Top 0.406: D27.A 49.37,16.67
  Top 1.27: 49.37,16.67 D26.K
N$22
  Top 0.406: 48.1,13.33 D27.K
  Top 1.27: D28.A 48.1,13.33
N$23
  Top 0.406: D30.A 38.89,22.07
  Top 1.27: 38.89,22.07 D29.K
N$24
  Top 0.406: D31.A 40.8,16.83
  Top 1.27: 40.8,16.83 D30.K
N$25
  Top 0.406: 42.07,13.18 D31.K
  Top 1.27: D32.A 42.07,13.18
N$26
  Top 0.406: D34.A 28.58,28.26
  Top 1.27: 28.58,28.26 D33.K
N$27
  Top 0.406: D35.A 22.7,27.3
  Top 1.27: 22.7,27.3 D34.K
N$28
  Top 0.406: 19.21,26.67 D35.K
  Top 1.27: D36.A 19.21,26.67
N$29
  Top 0.406: D38.A 22.22,39.21
  Top 1.27: 22.22,39.21 D37.K
N$30
  Top 0.406: D39.A 18.42,34.61
  Top 1.27: 18.42,34.61 D38.K
N$31
  Top 0.406: 16.35,32.07 D39.K
  Top 1.27: D40.A 16.35,32.07
N$32
  Top 0.406: 23.49,49.37 D41.K
  Top 1.27: D42.A 23.49,49.37
N$33
  Top 0.406: 20,53.66 D42.K
  Top 1.27: D43.A 20,53.66
N$34
  Top 0.406: D43.K 16.03,58.42
  Top 1.27: 16.03,58.42 D44.A
N$35
  Top 0.406: D46.A 28.58,61.91
  Top 1.27: 28.58,61.91 D45.K
N$36
  Top 0.406: D47.A 22.54,63.02
  Top 1.27: 22.54,63.02 D46.K
N$37
  Top 0.406: D48.A 16.99,63.98
  Top 1.27: 16.99,63.98 D47.K
N$38
  Top 0.406: 42.86,71.12 D49.A
  Top 1.27: D50.K 42.86,71.12
N$39
  Top 0.406: 49.37,65.72 D53.A
  Top 1.27: D52.K 49.37,65.72
N$40
  Top 0.406: D53.K 48.1,69.06
  Top 1.27: 48.1,69.06 D54.A
N$41
  Top 0.406: D55.K 58.74,58.58
  Top 1.27: 58.74,58.58 D56.A
N$42
  Top 0.406: 66.68,60.01 D57.A
  Top 1.27: D56.K 66.68,60.01
N$43
  Top 0.406: 65.09,51.59 D59.A
  Top 1.27: D58.K 65.09,51.59
N$44
  Top 0.406: 68.9,56.04 D60.A
  Top 1.27: D59.K 68.9,56.04
N$45
  Top 0.406: D62.A 65.09,38.42
  Top 1.27: 65.09,38.42 D61.K
N$46
  Top 0.406: D63.A 68.74,33.97
  Top 1.27: 68.74,33.97 D62.K
N$47
  Top 0.406: D65.A 60.64,31.11
  Top 1.27: 60.64,31.11 D64.K
N$48
  Top 0.406: 66.52,30 D66.A
  Top 1.27: D65.K 66.52,30
N$49
  Top 0.406: 50.32,26.99 D67.K
  Top 1.27: D68.A 50.32,26.99
N$50
  Top 0.406: 48.1,21.11 D68.K
  Top 1.27: D69.A 48.1,21.11
N$51
  Top 0.406: 40.01,26.83 D70.K
  Top 1.27: D71.A 40.01,26.83
N$52
  Top 0.406: D72.A 42.86,19.05
  Top 1.27: 42.86,19.05 D71.K
N$53
  Top 0.406: D74.A 29.53,31.11
  Top 1.27: 29.53,31.11 D73.K
N$54
  Top 0.406: 26.03,30.48 D74.K
  Top 1.27: D75.A 26.03,30.48
N$55
  Top 0.406: 26.51,40.32 D76.K
  Top 1.27: D77.A 26.51,40.32
N$56
  Top 0.406: D78.A 21.27,33.97
  Top 1.27: 21.27,33.97 D77.K
N$57
  Top 0.406: D80.A 29.37,58.9
  Top 1.27: 29.37,58.9 D79.K
N$58
  Top 0.406: 25.88,59.53 D80.K
  Top 1.27: D81.A 25.88,59.53
N$59
  Top 0.406: D83.A 25.24,51.28
  Top 1.27: 25.24,51.28 D82.K
N$60
  Top 0.406: 21.43,56.04 D84.A
  Top 1.27: D83.K 21.43,56.04
N$61
  Bottom 0.406: ISP.2 38.26,40.32 45.24,47.31 45.24,48.74 46.04,49.53 IO3.1 47.31,49.53
N$67
  Top 0.406: D85.K 42.07,61.12
  Top 1.27: 42.07,61.12 D86.A
N$68
  Top 0.406: D86.K 43.97,66.67
  Top 1.27: 45.08,69.53 D87.A
  Top 1.422: 43.97,66.67 45.08,69.53
N$69
  Top 0.406: 47.31,63.34 D87.K
  Top 1.27: D88.A 47.31,63.34
N$71
  Top 0.406: 61.91,52.07 D90.A
  Top 1.27: D89.K 61.91,52.07
N$72
  Top 0.406: D91.A 63.18,56.67
  Top 1.27: D90.K 66.36,57.31 63.18,56.67
N$73
  Top 0.406: 59.85,56.2 D91.K
  Top 1.27: D92.A 59.85,56.2
N$74
  Top 0.406: 60.48,39.69 D93.K
  Top 1.27: D94.A 60.48,39.69
N$75
  Top 0.406: 64.13,35.24 D94.K
  Top 1.27: D95.A 66.2,32.86 64.13,35.24
N$76
  Top 0.406: D96.A 57.47,34.45
  Top 1.27: 57.47,34.45 D95.K
N$77
  Top 0.406: D98.A 42.86,26.83
  Top 1.27: 42.86,26.83 D97.K
N$78
  Top 0.406: 46.2,23.5 D99.A
  Top 1.27: D98.K 45.08,20.64 46.2,23.5
N$79
  Top 0.406: 48.26,29.21 D100.A
  Top 1.27: D99.K 48.26,29.21
N$80
  Top 0.406: 32.86,34.45 D101.K
  Top 1.27: D102.A 32.86,34.45
N$81
  Top 0.406: 26.99,33.34 D102.K
  Top 1.27: D103.A 23.97,32.86 26.99,33.34
N$82
  Top 0.406: D103.K 28.1,37.94
  Top 1.27: 28.1,37.94 D104.A
N$83
  Top 0.406: 32.86,55.72 D105.K
  Top 1.27: D106.A 32.86,55.72
N$84
  Top 0.406: 26.99,56.83 D106.K
  Top 1.27: D107.A 23.81,57.31 26.99,56.83
N$85
  Top 0.406: D108.A 29.69,50.48
  Top 1.27: 29.69,50.48 D107.K
N$88
  Bottom 0.406: 47.31,48.26 48.58,48.26 49.85,49.53 R2.1 | 47.31,48.26 47.3,48.26 | IO3.2 47.3,48.27 47.31,48.26
N$89
  Bottom 0.406: 58.42,49.85 59.37,49.85
N$91
  Bottom 0.406: R3.2 47.62,56.2 T3.2
N$92
  Bottom 0.406: T3.3 | T3.3 43.5,58.42 R13A.1 43.5,58.74 43.5,60.64 R13B.1
N$93
  Bottom 0.406: T1.3 57.79,51.12 | T1.3 | T1.3 59.05,51.12 60.64,52.7 65.41,52.7 | 66.99,54.29 66.99,54.31 R11B.1 66.99,54.61 65.41,52.7 | 65.41,52.7 65.41,52.67 R11A.1
N$94
  Bottom 0.406: R12A.1 | T2.3 57.79,54.93 R12A.1 | R12A.1 | R12A.1 R12B.1
N$95
  Bottom 0.406: R1.2 54.29,46.99 56.2,48.9 T1.2
N$96
  Bottom 0.406: R2.2 53.34,51.12 53.34,52.39 54.93,53.98 T2.2 | T2.2 | T2.2
N$97
  Bottom 0.406: 47.62,46.99 47.3,46.99 | 47.62,46.99 R1.1 | IO3.3 47.62,47 47.62,46.99
N$98
  Bottom 0.406: ISP.3 38.73,42.86 39.69,43.81 39.69,45.4 40.01,45.72 IO3.5
N$99
  Bottom 0.406: ISP.4 38.1,45.4 39.69,46.99 IO3.6 42.86,46.99 44.13,48.26 44.13,50.8 46.04,52.7 R3.1 | R3.1
N$101
  Bottom 0.406: 62.23,50.48 62.23,49.21
N$102
  Bottom 0.406: 61.59,49.85 62.87,49.85
N$103
  Top 1.27: 20.16,60.64 17.3,61.12 18.89,59.05
N$104
  Top 1.27: 19.21,31.43 17.3,29.05 20.32,29.53
N$105
  Top 1.27: 12.38,27.46 10.64,25.24 13.81,25.72
N$106
  Top 1.27: 77.63,27.62 79.53,25.24 76.52,25.56
N$107
  Top 1.27: 69.85,29.37 72.87,29.05 70.96,31.43
N$112
  Top 1.27: 57.31,46.67 56.04,45.09 57.31,43.5
N$113
  Top 1.27: 43.97,74.29 45.08,77.15 46.2,74.29
N$114
  Top 1.27: 43.97,81.91 45.08,84.93 46.2,81.91
N$121
  Bottom 0.406: R4.2 41.59,55.56 41.59,55.88 T4.2
N$122
  Bottom 0.406: 35.88,54.93 | 35.88,54.93 R14A.1 | T4.3 | 35.88,54.93 T4.3 | R14A.1 | R14B.1 35.88,53.02 35.88,54.93 | 35.88,54.93 R14A.1 | R14A.1
N$123
  Bottom 0.406: R4.1 | R4.1 42.39,52.39 43.02,51.75 43.02,48.9 42.39,48.26 IO3.7 39.05,48.26 38.73,47.94 ISP.5 36.51,48.26

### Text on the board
Top: TOP
Bottom: 2010 | PaJa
